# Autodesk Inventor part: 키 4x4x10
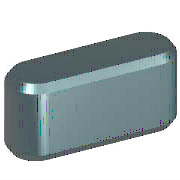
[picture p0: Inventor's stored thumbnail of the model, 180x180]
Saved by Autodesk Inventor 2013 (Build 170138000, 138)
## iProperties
IsCustomPart: 1
Created: 2012-02
Part Number: 키 4x4x10
Material: 강철, 연강
Description: 키 및 해당 키홈
Document SubType Name: Modeling
Standard: KS B 1311
Designer: test
Standards Organization: KS
Language: ko-KR
Size Designation: 4 x 4 x 10
Categories: <MemberInstance><Categories><Category DisplayName="샤프트 부품" InternalName="7f7aeb1f-a693-4053-b835-cee3144e0d98" Mnemonic="SHFT"><Category DisplayName="키" Interna
Density: 1 g/cm^3
Author: test
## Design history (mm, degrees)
workplane "Work Plane1"
workplane "Work Plane2"
sketch "스케치1"
  geometry: L1 (2, 2)-(8, 2); L2 (8, -2)-(2, -2); L3 (0, 9.4)-(0, -7.4) reference; L4 (-5, 0)-(30, 0) reference; L5 (10, 0)-(10, 7); A1 r 2 centre (2, 0) between (2, 2) and (2, -2); A2 r 2 centre (8, 0) between (8, -2) and (8, 2)
  constraints: 6 end point, 5 point on circle, 4 tangent, 3 point on line, 2 centre point, 1 horizontal, 1 parallel, 1 perpendicular
  dimensions: "d0" = 2 radius of A1 (= 0.5 x PB); "d13" = 2 radius of A2 (= 0.5 x PB); "d14" = 10 distance between parallel lines of L5 L3 (= NLG)
extrude "본체1" new body sketch "스케치1" taper "d3" = 0 deg; stored distance "d4" = 10
workplane "Work Plane3"
body "Solid1"
chamfer "모따기1" distance "d8" = 0.25 (= PHH); stored, may be unused: second distance "d9" = 0.25 (= PHH), angle "d15" = 45 deg
other parameters: "d1" = -2.5 (= -PNT), "d2" = 1.5 (= PH - PNT), "NLG" = 10 [user parameter; used in 3 equation terms], "PB" = 4 [user parameter; used in 2 equation terms], "PNT" = 2.5 [user parameter; used in 2 equation terms], "PH" = 4 [user parameter; used in 1 equation term], "PHH" = 0.25 [user parameter; used in 2 equation terms], "d10" = 0, "d16" = 0, "d17" = 0, "d18" = 0, "WDMAX" = 12 [user parameter], "RR" = 0.08 [user parameter], "PUEB" = 1.8 [user parameter]
